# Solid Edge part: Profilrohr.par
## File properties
Username: bmolnar
Dokumentum tartalom típus: 0
Author: bmolnar
Last saved by: bmolnar
Revision: 98
Sűrűség: 0,000 kg/m^3
Pontosság: 0,990
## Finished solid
Body 1: solid body, 115 faces, 338 edges, 224 vertices.
  Faces by surface: cylinder 59, plane 56
  Edges by curve: line 220, circle 118
Bounding box of the edges (mm): 113.500 x 113.500 x 528.000, from (-56.75, -56.75, -511.5) to (56.75, 56.75, 16.5).
Cylindrical faces by radius (mm): R0.15 x24, R0.25 x24, R1 x4, R12.25 x4, R35 x2, R50 x1
Planar faces by outward normal: +x 13, +y 14, +z 1, -x 13, -y 14, -z 1
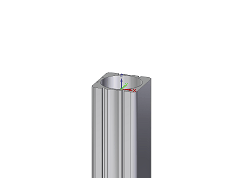
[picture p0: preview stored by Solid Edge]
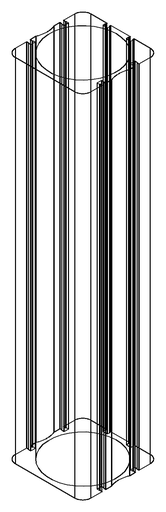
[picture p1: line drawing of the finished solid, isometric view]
